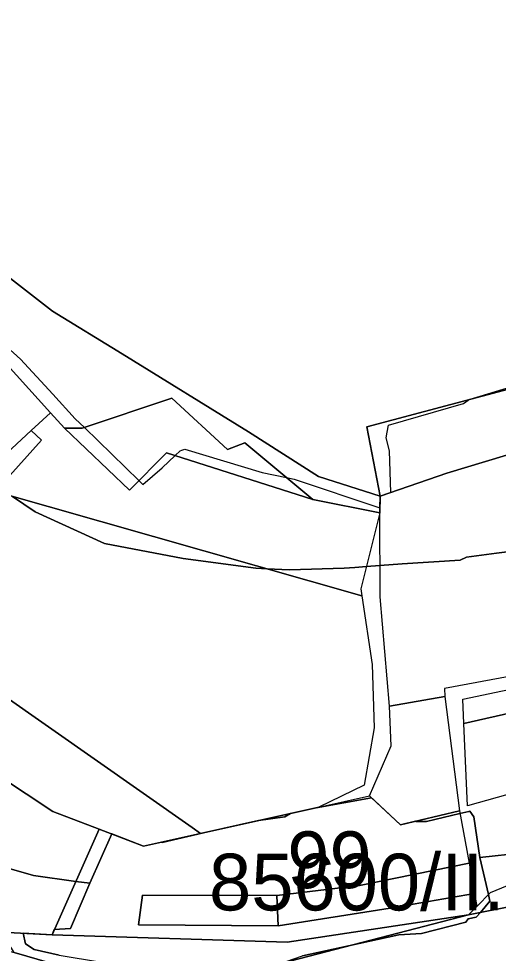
# Model space of a CAD drawing. Extents: x -477304 to -465429, y -1159113 to -1149210.
# Drawn here: x -473968.5 to -473841.7, y -1153880.4 to -1153633.1 of the extents above; entities that cross this region are included whole.
import ezdxf

# ---------------------------------------------------------------- set-up
doc = ezdxf.new("R2010")
doc.units = 0
for name, color, linetype in [('BPEJ_s', 7, 'Continuous'), ('orna_s', 7, 'Continuous'), ('PUPFL_s', 7, 'Continuous'), ('trav_porost_s', 7, 'Continuous'), ('voda_s', 7, 'Continuous')]:
    doc.layers.add(name, color=color, linetype=linetype)

msp = doc.modelspace()

# ---------------------------------------------------------------- linework, layer by layer
at = {"layer": 'BPEJ_s'}
for points in [[(-473982.81, -1153709.9), (-473967.96, -1153723.18), (-473959.43, -1153732.47), (-473953.5, -1153738.93), (-473951.09, -1153741.27), (-473936.66, -1153755.34), (-473935.67, -1153756.31), (-473930.51, -1153751.91), (-473927.13, -1153748.68), (-473925.83, -1153747.44), (-473925.36, -1153747.28), (-473924.56, -1153747.01), (-473904.13, -1153753.18), (-473897.7, -1153754.47), (-473895.62, -1153754.89), (-473873.03, -1153762.49), (-473872.95, -1153759.4), (-473870.13, -1153758.43), (-473870.51, -1153747.44), (-473871.36, -1153744.03), (-473871.08, -1153742.51), (-473870.73, -1153740.63), (-473850.94, -1153734.88), (-473849.68, -1153733.99), (-473849.45, -1153733.82), (-473837.53, -1153730.2)], [(-473982.81, -1153709.9), (-473967.96, -1153723.18), (-473959.43, -1153732.47), (-473953.5, -1153738.93), (-473951.09, -1153741.27), (-473936.66, -1153755.34), (-473935.67, -1153756.31), (-473930.51, -1153751.91), (-473927.13, -1153748.68), (-473925.83, -1153747.44), (-473925.36, -1153747.28), (-473924.56, -1153747.01), (-473904.13, -1153753.18), (-473897.7, -1153754.47), (-473895.62, -1153754.89), (-473873.03, -1153762.49), (-473872.95, -1153759.4), (-473870.13, -1153758.43), (-473870.51, -1153747.44), (-473871.36, -1153744.03), (-473871.08, -1153742.51), (-473870.73, -1153740.63), (-473850.94, -1153734.88), (-473849.68, -1153733.99), (-473849.45, -1153733.82), (-473837.53, -1153730.2)], [(-473970.06, -1153759.49), (-473964.14, -1153763.61), (-473945.83, -1153771.91), (-473924.98, -1153775.95), (-473905.83, -1153778.5), (-473902.9, -1153778.64), (-473896.9, -1153778.93), (-473882.43, -1153778.5), (-473879.67, -1153778.29), (-473876.56, -1153778.05), (-473872.98, -1153777.77), (-473867.1, -1153777.31), (-473851.79, -1153776.38), (-473850.08, -1153775.53), (-473842.21, -1153774.54), (-473836.47, -1153773.82)], [(-473851.79, -1153776.38), (-473867.1, -1153777.31), (-473872.98, -1153777.77), (-473876.56, -1153778.05), (-473879.67, -1153778.29), (-473882.43, -1153778.5), (-473896.9, -1153778.93), (-473902.9, -1153778.64), (-473905.83, -1153778.5), (-473924.98, -1153775.95), (-473945.83, -1153771.91), (-473964.14, -1153763.61), (-473970.06, -1153759.49)], [(-473836.47, -1153773.82), (-473842.21, -1153774.54), (-473850.08, -1153775.53), (-473851.79, -1153776.38)], [(-473957.75, -1153880.85), (-473964.35, -1153879.36), (-473966.69, -1153877.87), (-473967.25, -1153875.08), (-473959.66, -1153875.49), (-473959.05, -1153874.12), (-473954.77, -1153873.83), (-473949.68, -1153861.86), (-473943.89, -1153848.82), (-473935.5, -1153852.08), (-473930.68, -1153851), (-473930.51, -1153851.06), (-473919.6, -1153848.53), (-473905.06, -1153845.29), (-473898.17, -1153844.25), (-473896.61, -1153843.4), (-473889.84, -1153841.89), (-473875.22, -1153839.25), (-473867.59, -1153846.4), (-473863.58, -1153845.45), (-473863.49, -1153845.53), (-473860.73, -1153845.53), (-473851.84, -1153843.39), (-473849.54, -1153842.84), (-473849.23, -1153842.76), (-473848.17, -1153844.25), (-473846.61, -1153855), (-473844.32, -1153864.85), (-473843.91, -1153866.59), (-473846.43, -1153869.56), (-473847.53, -1153870.85), (-473849.66, -1153871.28), (-473850.3, -1153872.13), (-473862, -1153875.11), (-473867.96, -1153875.53), (-473881.33, -1153878.43), (-473893.49, -1153881.06)], [(-473835.19, -1153853.83), (-473846.61, -1153855), (-473848.17, -1153844.25), (-473849.23, -1153842.76), (-473849.54, -1153842.84), (-473851.84, -1153843.39), (-473860.73, -1153845.53), (-473863.49, -1153845.53), (-473863.58, -1153845.45), (-473867.59, -1153846.4), (-473875.22, -1153839.25), (-473889.84, -1153841.89), (-473896.61, -1153843.4), (-473898.17, -1153844.25), (-473905.06, -1153845.29), (-473919.6, -1153848.53), (-473930.51, -1153851.06), (-473930.68, -1153851), (-473935.5, -1153852.08), (-473943.89, -1153848.82), (-473949.68, -1153861.86), (-473953.37, -1153861.35)], [(-473966.69, -1153877.87), (-473964.35, -1153879.36), (-473957.75, -1153880.85), (-473923.19, -1153886.61), (-473920.73, -1153887.02), (-473903.55, -1153883.68), (-473897.75, -1153882.55), (-473893.49, -1153881.06), (-473881.33, -1153878.43), (-473867.96, -1153875.53), (-473862, -1153875.11), (-473850.3, -1153872.13), (-473849.66, -1153871.28), (-473847.53, -1153870.85), (-473846.43, -1153869.56), (-473843.91, -1153866.59), (-473844.32, -1153864.85), (-473846.61, -1153855), (-473835.19, -1153853.83)], [(-473953.37, -1153861.35), (-473964.56, -1153859.79), (-473974.12, -1153857.09)], [(-473974.12, -1153857.09), (-473964.56, -1153859.79), (-473953.37, -1153861.35), (-473949.68, -1153861.86), (-473954.77, -1153873.83), (-473959.05, -1153874.12), (-473959.66, -1153875.49), (-473967.25, -1153875.08), (-473966.69, -1153877.87)]]:
    msp.add_lwpolyline(points, dxfattribs=at)
for points in [[(-473900.2, -1153865.12), (-473935.72, -1153864.98), (-473936.76, -1153872.87), (-473899.93, -1153873.1)], [(-473900.2, -1153865.12), (-473899.93, -1153873.1), (-473936.76, -1153872.87), (-473935.72, -1153864.98)]]:
    msp.add_lwpolyline(points, close=True, dxfattribs=at)
at = {"layer": 'orna_s'}
for points in [[(-473796.82, -1153826.45), (-473849.84, -1153841.35), (-473850.8, -1153819.57), (-473689.77, -1153783.02), (-473686.13, -1153800.96), (-473746.01, -1153814.46), (-473777.12, -1153820.91)], [(-473899.93, -1153873.1), (-473936.76, -1153872.87), (-473935.72, -1153864.98), (-473900.2, -1153865.12)]]:
    msp.add_lwpolyline(points, close=True, dxfattribs=at)
at = {"layer": 'PUPFL_s'}
for points in [[(-473317.9, -1153181.74), (-473336.03, -1153216.76), (-473345.77, -1153242.45), (-473360.35, -1153318.85), (-473425.22, -1153434.63), (-473427.02, -1153440.19), (-473427.69, -1153442.92), (-473433.83, -1153466.27), (-473506.84, -1153474.05), (-473574.91, -1153481.82), (-473579.34, -1153482.33), (-473644.06, -1153489.73), (-473629.89, -1153542.49), (-473625.46, -1153559), (-473742.33, -1153616.45), (-473722.79, -1153641.99), (-473823.78, -1153727.09), (-473876.42, -1153741.11), (-473872.95, -1153759.4), (-473889.2, -1153754.19), (-473907.69, -1153742.41)], [(-473907.69, -1153742.41), (-473941.13, -1153721.8), (-473959.5, -1153710.48), (-473978.64, -1153695.63), (-473993.79, -1153702.69), (-473996.1, -1153703.76), (-474005.41, -1153685.4), (-474007.19, -1153681.89), (-474013.18, -1153684.64), (-474018.73, -1153672.6), (-473996.2, -1153665.65), (-473985.18, -1153667.66), (-473992.8, -1153643.11), (-473991.36, -1153629.33)]]:
    msp.add_lwpolyline(points, dxfattribs=at)
for points in [[(-473772.87, -1153717.61), (-473781.67, -1153723.51), (-473806.16, -1153737.16), (-473819.14, -1153742.37), (-473855.33, -1153753.34), (-473872.95, -1153759.4), (-473876.42, -1153741.11), (-473823.78, -1153727.09), (-473722.79, -1153641.99), (-473716.48, -1153650.25), (-473736.96, -1153677.1), (-473743.44, -1153686.38), (-473757.62, -1153702.35), (-473759.18, -1153703.96), (-473765.34, -1153710.29)], [(-473908.69, -1153745.3), (-473913.25, -1153747.06), (-473927.95, -1153733.48), (-473951.66, -1153741.46), (-473956.35, -1153741.42), (-473960.03, -1153737.37), (-473978.12, -1153717.47), (-473993.79, -1153702.69), (-473978.64, -1153695.63), (-473959.5, -1153710.48), (-473941.13, -1153721.8), (-473907.69, -1153742.41), (-473889.2, -1153754.19), (-473872.95, -1153759.4), (-473873.06, -1153763.83), (-473890.75, -1153760.27)], [(-473956.35, -1153741.42), (-473951.66, -1153741.46), (-473927.95, -1153733.48), (-473913.25, -1153747.06), (-473908.69, -1153745.3), (-473890.75, -1153760.27), (-473929.39, -1153747.96), (-473939.17, -1153757.88)], [(-473956.35, -1153741.42), (-473939.17, -1153757.88), (-473929.39, -1153747.96), (-473890.75, -1153760.27), (-473873.06, -1153763.83), (-473878.02, -1153783.97), (-473877.74, -1153785.82), (-473974.69, -1153758.17), (-473962.43, -1153744.64), (-473965.18, -1153742.09), (-473960.03, -1153737.37)], [(-473847.35, -1153868.02), (-473849.63, -1153870.19), (-473897.54, -1153877.44), (-473959.66, -1153875.49), (-473947.22, -1153847.53), (-473935.5, -1153852.08), (-473920.46, -1153848.72), (-473889.11, -1153841.73), (-473875.75, -1153838.75), (-473867.59, -1153846.4), (-473851.97, -1153842.69), (-473849.44, -1153856.54), (-473878.42, -1153862.41), (-473900.2, -1153865.12), (-473935.72, -1153864.98), (-473936.76, -1153872.87), (-473899.93, -1153873.1), (-473870.26, -1153868.41), (-473847.98, -1153864.55)], [(-473878.42, -1153862.41), (-473849.44, -1153856.54), (-473847.98, -1153864.55), (-473870.26, -1153868.41), (-473899.93, -1153873.1), (-473900.2, -1153865.12)], [(-473898.84, -1153882.98), (-473926.07, -1153887.04), (-473960.25, -1153882.89), (-473969.67, -1153880.22), (-473973.05, -1153874.77), (-473959.66, -1153875.49), (-473897.54, -1153877.44), (-473849.63, -1153870.19)]]:
    msp.add_lwpolyline(points, close=True, dxfattribs=at)
at = {"layer": 'trav_porost_s'}
for points in [[(-473978.12, -1153717.47), (-473960.03, -1153737.37), (-473965.18, -1153742.09), (-473975.48, -1153751.54), (-473999.55, -1153725.7), (-473989.14, -1153714.74), (-473996.1, -1153703.76), (-473993.79, -1153702.69)], [(-473855.82, -1153812.4), (-473870.49, -1153815.01), (-473872.93, -1153786.05), (-473873.06, -1153763.83), (-473872.95, -1153759.4), (-473855.33, -1153753.34), (-473819.14, -1153742.37), (-473806.16, -1153737.16), (-473781.67, -1153723.51), (-473772.87, -1153717.61), (-473701.8, -1153768.21), (-473725.74, -1153775.26), (-473750.81, -1153780.66), (-473808.33, -1153799.28), (-473831.3, -1153805.72), (-473855.95, -1153810.35)], [(-473999.55, -1153725.7), (-473975.48, -1153751.54), (-473965.18, -1153742.09), (-473962.43, -1153744.64), (-473974.69, -1153758.17), (-473979, -1153755.56), (-473989.3, -1153749.33), (-473991.98, -1153744.05), (-473998.03, -1153736.07), (-474000.67, -1153732.44), (-474005.41, -1153735.89), (-474007.19, -1153733.45), (-474012.71, -1153737.46)], [(-473922.62, -1153847.07), (-474011.57, -1153784.78), (-473979, -1153755.56), (-473974.69, -1153758.17), (-473877.74, -1153785.82), (-473875.04, -1153803.95), (-473874.54, -1153820.69), (-473877.16, -1153835.89), (-473889.11, -1153841.73), (-473920.46, -1153848.72)], [(-473667.02, -1153786.39), (-473673.22, -1153788.66), (-473676.41, -1153789.83), (-473675.42, -1153792.54), (-473674.73, -1153794.41), (-473671.37, -1153793.18), (-473669.96, -1153797.32), (-473686.13, -1153800.96), (-473689.77, -1153783.02), (-473850.8, -1153819.57), (-473851.08, -1153813.13), (-473830.09, -1153808.7), (-473805.39, -1153802.8), (-473763.73, -1153788.17), (-473725.74, -1153775.26), (-473701.8, -1153768.21), (-473676.23, -1153761.51), (-473667.78, -1153778.92)], [(-473935.5, -1153852.08), (-473947.22, -1153847.53), (-473959.45, -1153842.89), (-473973.61, -1153833.55), (-473977.75, -1153824.58), (-473986.64, -1153821.6), (-474007.78, -1153822.76), (-474003.88, -1153815.35), (-474001.83, -1153805.97), (-474001.56, -1153801.92), (-474015.4, -1153793.35), (-474011.57, -1153784.78), (-473922.62, -1153847.07), (-473920.46, -1153848.72)], [(-473870.05, -1153825.46), (-473870.49, -1153815.01), (-473855.82, -1153812.4), (-473851.97, -1153842.69), (-473867.59, -1153846.4), (-473875.75, -1153838.75)], [(-473947.22, -1153847.53), (-473959.66, -1153875.49), (-473973.05, -1153874.77), (-473978.88, -1153863.97), (-473971.17, -1153852.83), (-473986.97, -1153840.23), (-473995.81, -1153830.53), (-474012.45, -1153823.5), (-474007.78, -1153822.76), (-473986.64, -1153821.6), (-473977.75, -1153824.58), (-473973.61, -1153833.55), (-473959.45, -1153842.89)]]:
    msp.add_lwpolyline(points, close=True, dxfattribs=at)
at = {"layer": 'voda_s'}
msp.add_lwpolyline([(-473788.82, -1153858.15), (-473849.63, -1153870.19), (-473847.35, -1153868.02), (-473843.76, -1153864.26), (-473826.7, -1153857.24), (-473799.19, -1153852.44), (-473796.9, -1153852.26), (-473770.58, -1153850.14), (-473770.29, -1153851.19), (-473747.94, -1153853.1)], close=True, dxfattribs=at)
msp.add_lwpolyline([(-474165.39, -1153867.04), (-474084.14, -1153854.43), (-474075.98, -1153856.54), (-474082.42, -1153862.08), (-474032.41, -1153869.61), (-474028.31, -1153870.23), (-474021.95, -1153871.19), (-473994.36, -1153873.21), (-473969.67, -1153880.22), (-473960.25, -1153882.89), (-473926.07, -1153887.04), (-473898.84, -1153882.98), (-473849.63, -1153870.19), (-473788.82, -1153858.15)], dxfattribs=at)

# ---------------------------------------------------------------- texts
at = {"layer": 'BPEJ_s'}
for s, p in [('99', (-473897.47, -1153863.14)), ('85600/II.', (-473918.16, -1153869.04))]:
    msp.add_text(s, height=15, dxfattribs=at).set_placement(p)

doc.saveas('drawing.dxf')
